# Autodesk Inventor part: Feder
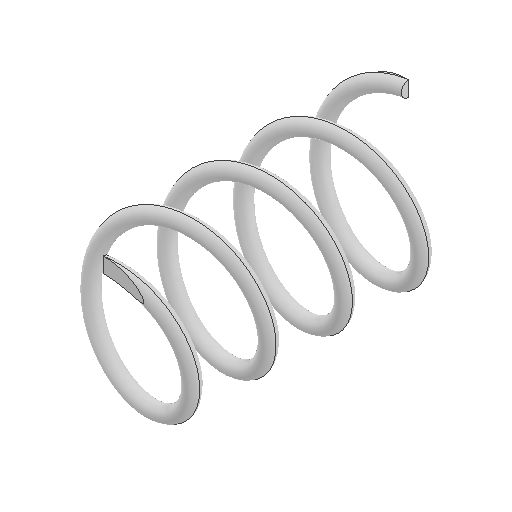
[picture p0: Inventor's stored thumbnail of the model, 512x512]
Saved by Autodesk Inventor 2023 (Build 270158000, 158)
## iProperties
Created: 2023-02
Part Number: Feder
Material: Generisch
Document SubType Name: Modeling
Designer: Nicole Höfler
Density: 1 g/cm^3
Appearance: Vorgabe
Author: Nicole Höfler
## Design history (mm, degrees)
sketch "Skizze1"
  geometry: C1 r 2.5 at (0, 0); 1 further point
  constraints: 1 centre point, 1 coincident
  dimensions: "d0" = 5 diameter of C1
extrude "Extrusion1" new body sketch "Skizze1" taper "d2" = 0 deg; distance "Höhe" = 10
sketch "Skizze2"
  geometry: L1 (2.5, 0)-(2.5, 10) reference; L2 (2.5, 0)-(-2.5, 0) reference; L3 (0, 0)-(0, 24); C1 r 0.25 at (2.25, 0)
  constraints: 2 end point, 1 centre point, 1 point on line, 1 tangent, 1 vertical
  dimensions: "d3" = 0.5 diameter of C1
feature "Spirale1" sketch "Skizze2" pitch "d4" = 2.5; turns "d6" = 1; dims "d5" = 10 (= Höhe), "d7" = 0, angle "d8" = 90 deg, angle "d9" = 90 deg, "d10" = 0, "d11" = 0
node "Volumenkörper1"
